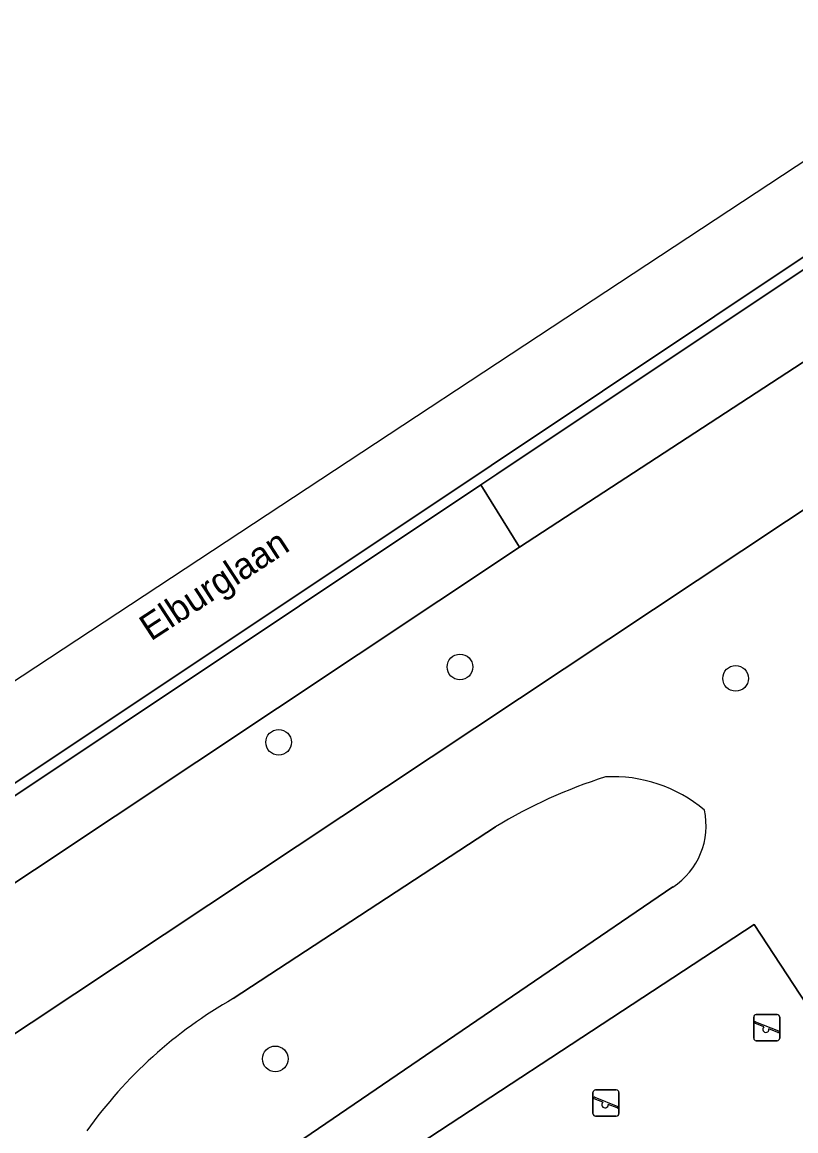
# Model space of a CAD drawing. Extents: x 158352 to 159489, y 383828 to 384603.
# Drawn here: x 158438.72 to 158468.16, y 384265.67 to 384307.86 of the extents above; entities that cross this region are included whole.
import ezdxf

# ---------------------------------------------------------------- set-up
doc = ezdxf.new("R2010")
doc.units = 0
for name, color, linetype in [('IMGEO_Boom', 7, 'Continuous'), ('IMGEO_Groenvoorziening', 7, 'Continuous'), ('IMGEO_Openbare_ruimte_label', 7, 'Continuous'), ('IMGEO_Parkeervlak_halfverhard', 7, 'Continuous'), ('IMGEO_Rijbaan_lokaal_gesloten', 7, 'Continuous'), ('IMGEO_Rijbaan_lokaal_halfverhard', 7, 'Continuous'), ('IMGEO_Speelvoorziening', 7, 'Continuous'), ('IMGEO_Terreindeel_gesloten', 7, 'Continuous')]:
    doc.layers.add(name, color=color, linetype=linetype)

msp = doc.modelspace()

# ---------------------------------------------------------------- linework, layer by layer
at = {"layer": 'IMGEO_Boom'}
for centre in [(158455.381, 384283.325), (158465.871, 384282.89), (158448.479, 384280.456), (158448.353, 384268.409)]:
    msp.add_circle(centre, 0.489, dxfattribs=at)
at = {"layer": 'IMGEO_Groenvoorziening'}
for points in [[(158473.62, 384298.305), (158469.591, 384299.206), (158469.54, 384299.171), (158456.786, 384290.663), (158456.169, 384290.251), (158457.646, 384287.879)], [(158476.263, 384294.498), (158473.62, 384298.305), (158457.646, 384287.879), (158429.971, 384269.474), (158424.94, 384265.357), (158427.196, 384261.9)], [(158485.58, 384244.531), (158468.579, 384233.386), (158449.591, 384262.378), (158466.581, 384273.526)]]:
    msp.add_lwpolyline(points, close=True, dxfattribs=at)
for points in [[(158475.372, 384290.572), (158477.757, 384292.342), (158477.222, 384293.117), (158476.263, 384294.498), (158427.196, 384261.9), (158434.147, 384253.366)], [(158456.73, 384277.235), (158446.749, 384270.703)], [(158446.749, 384270.703), (158456.73, 384277.235)], [(158446.72, 384263.523), (158454.631, 384268.914), (158463.481, 384274.95)], [(158463.481, 384274.95), (158454.631, 384268.914), (158446.72, 384263.523)]]:
    msp.add_lwpolyline(points, dxfattribs=at)
for centre, radius, start, end in [((158466.674, 384260.937), 19.091, 107.5428, 121.3884), ((158466.674, 384260.937), 19.091, 107.5428, 121.3884), ((158461.204, 384273.754), 5.395, 49.8781, 93.0236), ((158461.204, 384273.754), 5.395, 49.8781, 93.0236), ((158461.978, 384277.275), 2.769, 302.88, 12.596), ((158461.978, 384277.275), 2.769, 302.88, 12.596), ((158455.426, 384255.502), 17.503, 119.7174, 144.4839), ((158455.426, 384255.502), 17.503, 119.7174, 144.4839)]:
    msp.add_arc(centre, radius, start, end, dxfattribs=at)
at = {"layer": 'IMGEO_Parkeervlak_halfverhard'}
msp.add_lwpolyline([(158457.646, 384287.879), (158456.169, 384290.251), (158428.524, 384271.811), (158429.971, 384269.474)], close=True, dxfattribs=at)
at = {"layer": 'IMGEO_Rijbaan_lokaal_gesloten'}
for points in [[(158543.653, 384352.095), (158414.938, 384267.325), (158415.773, 384267.534), (158421.001, 384268.843)], [(158428.004, 384271.944), (158456.564, 384290.996), (158469.318, 384299.504), (158479.02, 384305.996), (158486.407, 384310.963), (158502.433, 384321.714), (158506.44, 384324.394), (158506.412, 384324.448), (158509.723, 384326.659), (158509.757, 384326.598), (158520.613, 384333.873), (158536.677, 384344.622), (158544.931, 384350.172), (158543.653, 384352.095)]]:
    msp.add_lwpolyline(points, dxfattribs=at)
at = {"layer": 'IMGEO_Rijbaan_lokaal_halfverhard'}
msp.add_lwpolyline([(158428.201, 384271.596), (158428.524, 384271.811), (158456.169, 384290.251), (158456.786, 384290.663), (158469.54, 384299.171), (158469.591, 384299.206), (158479.078, 384305.554), (158479.243, 384305.664), (158486.589, 384310.604), (158486.63, 384310.631), (158502.632, 384321.366), (158502.656, 384321.382), (158506.664, 384324.062), (158506.44, 384324.394), (158502.433, 384321.714), (158486.407, 384310.963), (158479.02, 384305.996), (158469.318, 384299.504), (158456.564, 384290.996), (158428.004, 384271.944)], dxfattribs=at)
at = {"layer": 'IMGEO_Speelvoorziening'}
for p, q in [((158466.559, 384269.198), (158466.559, 384269.998)), ((158466.559, 384269.998), (158466.559, 384269.198)), ((158466.659, 384270.098), (158467.449, 384270.098)), ((158467.449, 384270.098), (158466.659, 384270.098)), ((158467.549, 384269.998), (158467.549, 384269.198)), ((158467.549, 384269.198), (158467.549, 384269.998)), ((158466.942, 384269.626), (158466.603, 384269.763)), ((158466.628, 384269.823), (158467.504, 384269.47)), ((158467.48, 384269.41), (158467.14, 384269.547)), ((158467.449, 384269.098), (158466.659, 384269.098)), ((158466.659, 384269.098), (158467.449, 384269.098)), ((158460.441, 384266.327), (158460.441, 384267.127)), ((158460.441, 384267.127), (158460.441, 384266.327)), ((158460.541, 384267.227), (158461.331, 384267.227)), ((158461.331, 384267.227), (158460.541, 384267.227)), ((158461.431, 384267.127), (158461.431, 384266.327)), ((158461.431, 384266.327), (158461.431, 384267.127)), ((158460.824, 384266.755), (158460.485, 384266.892)), ((158460.51, 384266.952), (158461.386, 384266.599)), ((158461.362, 384266.539), (158461.022, 384266.676)), ((158461.331, 384266.227), (158460.541, 384266.227)), ((158460.541, 384266.227), (158461.331, 384266.227))]:
    msp.add_line(p, q, dxfattribs=at)
for centre, radius, start, end in [((158466.659, 384269.998), 0.1, 90, 180), ((158466.659, 384269.998), 0.1, 90, 180), ((158467.449, 384269.998), 0.1, 0, 90), ((158467.449, 384269.998), 0.1, 360, 90), ((158466.616, 384269.793), 0.0327, 68.078, 248.078), ((158467.021, 384269.536), 0.12, 130.9928, 5.1632), ((158466.659, 384269.198), 0.1, 180, 270), ((158466.659, 384269.198), 0.1, 180, 270), ((158467.449, 384269.198), 0.1, 270, 0), ((158467.449, 384269.198), 0.1, 270, 0), ((158467.492, 384269.44), 0.0327, 248.078, 68.078), ((158460.541, 384267.127), 0.1, 90, 180), ((158460.541, 384267.127), 0.1, 90, 180), ((158461.331, 384267.127), 0.1, 0, 90), ((158461.331, 384267.127), 0.1, 360, 90), ((158460.498, 384266.922), 0.0327, 68.078, 248.078), ((158460.903, 384266.665), 0.12, 130.9928, 5.1632), ((158461.374, 384266.569), 0.0327, 248.078, 68.078), ((158460.541, 384266.327), 0.1, 180, 270), ((158460.541, 384266.327), 0.1, 180, 270), ((158461.331, 384266.327), 0.1, 270, 0), ((158461.331, 384266.327), 0.1, 270, 0)]:
    msp.add_arc(centre, radius, start, end, dxfattribs=at)
at = {"layer": 'IMGEO_Terreindeel_gesloten'}
msp.add_lwpolyline([(158485.58, 384244.531), (158466.581, 384273.526), (158449.591, 384262.378), (158468.579, 384233.386)], close=True, dxfattribs=at)

# ---------------------------------------------------------------- texts
at = {"layer": 'IMGEO_Openbare_ruimte_label'}
msp.add_text('Elburglaan', height=1, rotation=33.1656, dxfattribs=at).set_placement((158443.616, 384284.288))

doc.saveas('drawing.dxf')
